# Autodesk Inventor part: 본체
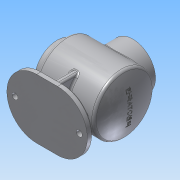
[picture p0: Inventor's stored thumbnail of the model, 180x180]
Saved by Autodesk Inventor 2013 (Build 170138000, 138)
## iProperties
Created: 2016-04
Part Number: 본체
Material: 알루미늄 6061
Document SubType Name: Modeling
Designer: Administrator
Density: 2.71 g/cm^3
Mass: 909.633 g
Surface Area: 1226.83 cm^2
Volume: 335.658 cm^3
Author: Administrator
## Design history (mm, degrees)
sketch "스케치1"
  geometry: L1 (-49, 0)-(-49, 50); L2 (-49, 50)-(50.087, 50); L3 (-49, 0)-(61, 0); A1 r 120 centre (-59, 0) between (61, 0) and (50.087, 50); 2 further points
  constraints: 6 end point, 2 horizontal alignment, 2 point on circle, 1 centre point, 1 coincident, 1 horizontal, 1 parallel, 1 vertical
  dimensions: "d9" = 240 diameter of A1; "d17" = 110 distance of L3.end L1.start; "d24" = 61 distance of L3.end point (0, 0); "d25" = 100 diameter of L2 L3
revolve "회전2" sketch "스케치1" stored, may be unused: angle "d27" = 90 deg
sketch "스케치3"
  geometry: C1 r 50 at (0, 0) reference; C2 r 38 at (0, 0)
  constraints: 1 centre point, 1 coincident
  dimensions: "d28" = 76 diameter of C2
feature "쉘2" dims "d30" = 3
extrude "돌출2" join sketch "스케치3" distance "d31" = 12; taper "d32" = 0 deg
node "작업 평면1"
sketch "스케치5"
  geometry: L1 (49, 50)-(49, -50) reference; C1 r 38 at (-1, 0); 1 further point
  constraints: 1 centre point, 1 horizontal alignment
  dimensions: "d115" = 76 diameter of C1; "d117" = 50 distance from line of L1 C1.centre
extrude "돌출4" join sketch "스케치5" stored distance "d40" = 15; taper "d41" = 0 deg
node "작업 평면2"
sketch "스케치9"
  geometry: L1 (-18.5, -50)-(16.5, -50); L2 (16.5, 50)-(-18.5, 50); A1 r 50 centre (16.5, 0) between (16.5, -50) and (16.5, 50); A2 r 50 centre (-18.5, 0) between (-18.5, 50) and (-18.5, -50); 2 further points
  constraints: 4 end point, 4 point on circle, 3 tangent, 2 centre point, 2 horizontal alignment, 1 coincident, 1 equal radius, 1 horizontal
  dimensions: "d69" = 135 dimension on A2 A1; "d71" = 50 radius of A2; "d159" = 18.5 distance of A2.centre point (0, 0)
extrude "돌출6" join sketch "스케치9" distance "d72" = 10; taper "d73" = 0 deg
sketch "스케치10"
  geometry: L1 (-4, 40)-(6, 40); L2 (6, 40)-(6, -40); L3 (6, -40)-(-4, -40); L4 (-4, -40)-(-4, 40); 2 further points
  constraints: 8 end point, 2 parallel, 1 horizontal, 1 horizontal alignment, 1 midpoint, 1 perpendicular
  dimensions: "d155" = 4 horizontal distance of L1.start point (0, 0); "d156" = 10 distance of L1.start L1.end; "d157" = 80 distance of L1.end L2.end
extrude "돌출7" join sketch "스케치10" stored distance "d77" = 10; taper "d78" = 0 deg
sketch "스케치11"
  geometry: L1 (-61, 38)-(-49, 38) reference; L2 (-61, -38)-(-61, 38) reference; L3 (-46, 47)-(-46, -47) reference; L4 (-46, -47)-(48.145, -47) reference; L5 (48.145, 47)-(-46, 47) reference; L6 (-37, 65)-(39, 65) reference; L7 (39, 50)-(50.087, 50) reference; L8 (50.087, -50)-(6, -50) reference; L9 (6, -69)-(68.5, -69) reference; L10 (68.5, -69)-(68.5, -79) reference; L11 (68.5, -79)-(-66.5, -79) reference; L12 (-66.5, -79)-(-66.5, -69) reference; L13 (-66.5, -69)-(-4, -69) reference; L14 (-4, -50)-(-49, -50) reference; L15 (-49, -50)-(-49, -38) reference; L16 (-49, -38)-(-61, -38) reference; L17 (-49, 38)-(-49, 50) reference; L18 (-49, 50)-(-37, 50) reference; L19 (-35.65, -50)-(-39, -69); L20 (37.65, -50)-(41, -69); L21 (39, 65)-(39, 50) reference; L22 (-37, 50)-(-37, 65) reference; L23 (6, -50)-(6, -69) reference; L24 (-4, -69)-(-4, -50) reference; A1 r 117 centre (-59, 0) between (48.145, -47) and (48.145, 47) reference; A2 r 120 centre (-59, 0) between (50.087, -50) and (50.087, 50) reference; 2 further points
  constraints: 4 end point, 4 point on line, 1 horizontal alignment
  dimensions: "d80" = 100 deg angle of L9 L20; "d82" = 100 deg angle of L13 L19; "d161" = 50 distance from line of L17 point (1, 0); "d162" = 40 horizontal distance of L19.end point (1, 0); "d163" = 40 horizontal distance of point (1, 0) L20.end
  node "절단 모서리 투영1"
feature "리브1" dims "d83" = 1, "d84" = 10, "d85" = 0, "d86" = 0, "d87" = 1, "d88" = 1
feature "리브2" dims "d89" = 1, "d90" = 10, "d91" = 0, "d92" = 0, "d93" = 1, "d94" = 1
fillet "모깎기1" dims "d95" = 2
fillet "모깎기2" dims "d96" = 5
fillet "모깎기4" dims "d98" = 3
chamfer "모따기1" distance "d99" = 3; stored, may be unused: second distance "d100" = 2, angle "d101" = 45 deg
sketch "스케치12"
  geometry: C1 r 5 at (-53, 0); 1 further point
  constraints: 1 centre point, 1 horizontal alignment
  dimensions: "d102" = 10 diameter of C1; "d104" = 53 distance of C1.centre point (0, 0)
extrude "돌출8" cut sketch "스케치12" stored distance "d105" = 10; taper "d106" = 0 deg
node "작업 평면3"
sketch "스케치13"
  geometry: 2 further points
  constraints: 1 coincident, 1 other
feature "엠보싱1" sketch "스케치13" dims "d9" = 240, "d17" = 110, "d24" = 61, "d25" = 100, "d110" = 0.5, "d111" = 0
sketch "스케치14"
  geometry: C1 r 38 at (0, 0) reference; C2 r 27 at (0, 0)
  constraints: 1 centre point, 1 coincident
  dimensions: "d118" = 54 diameter of C2
extrude "돌출9" cut sketch "스케치14" stored distance "d120" = 10; taper "d121" = 0 deg
sketch "스케치15"
  geometry: C1 r 27 at (0, 0) reference; 1 further point
  constraints: 1 vertical alignment
  dimensions: "d122" = 32.5 distance of C1.centre point (0, 32.5)
hole "구멍3" sketch "스케치15" at (0, 32.5) diameter "d123" = 3.242; stored, may be unused: countersink angle "d127" = 90 deg, drill point angle "d129" = 118 deg; dims "d124" = 8, "d125" = 4, "d126" = 2, "d128" = 10
chamfer "모따기3" distance "d133" = 1; stored, may be unused: second distance "d134" = 2, angle "d135" = 45 deg
sketch "스케치16"
  geometry: C1 r 38 at (0, 0) reference; C2 r 27 at (0, 0)
  constraints: 1 centre point, 1 coincident
  dimensions: "d136" = 54 diameter of C2
extrude "돌출10" cut sketch "스케치16" distance "d138" = 48; taper "d139" = 0 deg
sketch "스케치17"
  geometry: C1 r 27 at (0, 0) reference; 1 further point
  constraints: 1 vertical alignment
  dimensions: "d140" = 32.5 distance of C1.centre point (0, 32.5)
hole "구멍4" sketch "스케치17" at (0, 32.5) diameter "d141" = 3.242; stored, may be unused: countersink angle "d145" = 90 deg, drill point angle "d147" = 118 deg; dims "d142" = 8, "d143" = 4, "d144" = 2, "d146" = 10
chamfer "모따기4" distance "d151" = 1; stored, may be unused: second distance "d152" = 2, angle "d153" = 45 deg
fillet "모깎기5" dims "d154" = 3
fillet "모깎기6" dims "d164" = 5
fillet "모깎기7" dims "d165" = 3
node "솔리드2"
pattern_linear "직사각형 패턴1" dims "d109" = 108
pattern_circular "원형 패턴3" dims angle "d131" = 360 deg
pattern_circular "원형 패턴4" dims angle "d149" = 360 deg
other parameters: "d37" = 65, "d68" = -79
